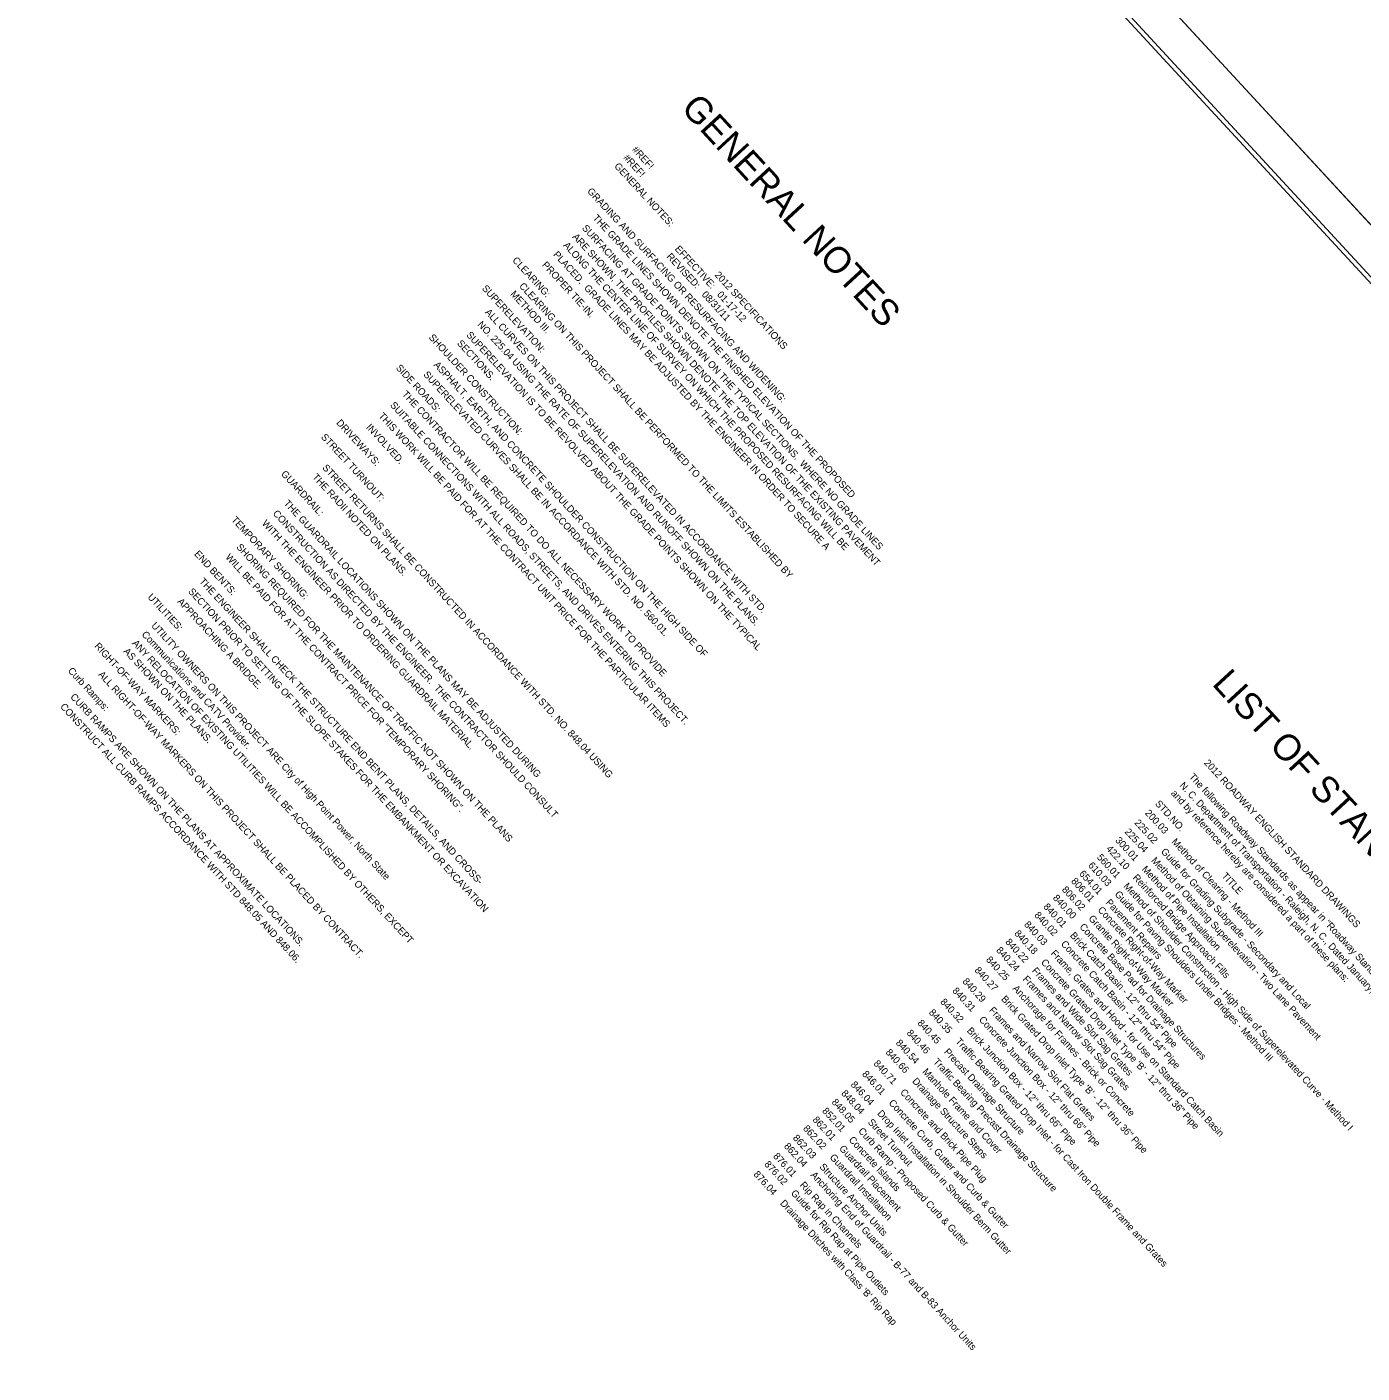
# Model space of a CAD drawing. Extents: x 1695041 to 1706254, y 786537 to 798223.
# Drawn here: x 1696581 to 1698101, y 794948 to 796480 of the extents above; entities that cross this region are included whole.
import ezdxf

# ---------------------------------------------------------------- set-up
doc = ezdxf.new("R2010")
doc.units = 0
for name, color, linetype in [('Old_Level_16', 7, 'Continuous'), ('Old_Level_23', 7, 'Continuous'), ('Sheet Cutting Line CELL', 7, 'Continuous'), ('Sheet Plan CELL', 7, 'Continuous'), ('Sheet Plot Border Inside CELL', 7, 'Continuous'), ('Sheet Plot Border Outside CELL', 7, 'Continuous')]:
    doc.layers.add(name, color=color, linetype=linetype)

msp = doc.modelspace()

# ---------------------------------------------------------------- linework, layer by layer
at = {"layer": 'Sheet Cutting Line CELL'}
msp.add_line((1698934.2, 795362), (1696650.4, 797836.1), dxfattribs=at)
at = {"layer": 'Sheet Plan CELL'}
msp.add_lwpolyline([(1698878.1, 795356.5), (1696843.2, 797560.9), (1695300.2, 796136.5), (1697335, 793932.1)], close=True, dxfattribs=at)
at = {"layer": 'Sheet Plot Border Inside CELL'}
msp.add_lwpolyline([(1695088.2, 796358.7), (1697348.3, 793910.3), (1698898.7, 795341.5), (1696638.7, 797789.9)], close=True, dxfattribs=at)
at = {"layer": 'Sheet Plot Border Outside CELL'}
msp.add_lwpolyline([(1695041.2, 796350.7), (1697325, 793876.6), (1698934.2, 795362), (1696650.4, 797836.1)], close=True, dxfattribs=at)

# ---------------------------------------------------------------- texts
at = {"layer": 'Old_Level_16'}
for s, p in [('                        GENERAL NOTES ', (1697143.1, 796582.8)), ('                        LIST OF STANDARD DRAWINGS ', (1697747.4, 795928.1))]:
    msp.add_text(s, height=30, rotation=312.7091, dxfattribs=at).set_placement(p)
at = {"layer": 'Old_Level_23'}
for s, p in [('#REF!', (1697269.5, 796339.4)), ('GENERAL NOTES:                         2012 SPECIFICATIONS', (1697249.2, 796320.7)), ('#REF!', (1697259.5, 796330.2)), ('GRADING AND SURFACING OR RESURFACING AND WIDENING:  ', (1697218.4, 796292.2)), ('         THE GRADE LINES SHOWN DENOTE THE FINISHED ELEVATION OF THE PROPOSED ', (1697206.6, 796281.4)), ('         SURFACING AT GRADE POINTS SHOWN ON THE TYPICAL SECTIONS.  WHERE NO GRADE LINES ', (1697194.3, 796270)), ('         ALONG THE CENTER LINE OF SURVEY ON WHICH THE PROPOSED RESURFACING WILL BE ', (1697173, 796250.3)), ('         ARE SHOWN, THE PROFILES SHOWN DENOTE THE TOP ELEVATION OF THE EXISTING PAVEMENT ', (1697183.4, 796260)), ('CLEARING:  ', (1697133.2, 796213.6)), ('         PLACED.  GRADE LINES MAY BE ADJUSTED BY THE ENGINEER IN ORDER TO SECURE A ', (1697161.6, 796239.8)), ('                                       REVISED:   08/31/11', (1697230.1, 796303.1)), ('                                       EFFECTIVE:   01-17-12', (1697239.5, 796311.7)), ('         PROPER TIE-IN.  ', (1697148.8, 796228)), ('SUPERELEVATION:  ', (1697098.6, 796181.7)), ('         CLEARING ON THIS PROJECT SHALL BE PERFORMED TO THE LIMITS ESTABLISHED BY ', (1697122.8, 796204)), ('         METHOD III.', (1697112.8, 796194.8)), ('         ALL CURVES ON THIS PROJECT SHALL BE SUPERELEVATED IN ACCORDANCE WITH STD. ', (1697083.9, 796174.2)), ('         NO. 225.04 USING THE RATE OF SUPERELEVATION AND RUNOFF SHOWN ON THE PLANS.', (1697075.4, 796160.2)), ('SHOULDER CONSTRUCTION:  ', (1697038.1, 796125.8)), ('         SUPERELEVATION IS TO BE REVOLVED ABOUT THE GRADE POINTS SHOWN ON THE TYPICAL ', (1697062.6, 796148.4)), ('         SECTIONS.  ', (1697052.1, 796138.8)), ('SIDE ROADS:  ', (1697000.7, 796091.3)), ('         ASPHALT, EARTH, AND CONCRETE SHOULDER CONSTRUCTION ON THE HIGH SIDE OF', (1697025.6, 796114.3)), ('         SUPERELEVATED CURVES SHALL BE IN ACCORDANCE WITH STD. NO. 560.01.', (1697013.8, 796103.3)), ('         THE CONTRACTOR WILL BE REQUIRED TO DO ALL NECESSARY WORK TO PROVIDE ', (1696989.6, 796081)), ('         SUITABLE CONNECTIONS WITH ALL ROADS, STREETS, AND DRIVES ENTERING THIS PROJECT.  ', (1696976, 796068.5)), ('DRIVEWAYS:  ', (1696932.9, 796028.7)), ('         THIS WORK WILL BE PAID FOR AT THE CONTRACT UNIT PRICE FOR THE PARTICULAR ITEMS ', (1696962.8, 796056.3)), ('         INVOLVED.  ', (1696948.7, 796043.3)), ('STREET TURNOUT:  ', (1696915.5, 796012.6)), ('GUARDRAIL:  ', (1696870, 795970.6)), ('         THE RADII NOTED ON PLANS.  ', (1696887.4, 795986.7)), ('         STREET RETURNS SHALL BE CONSTRUCTED IN ACCORDANCE WITH STD. NO. 848.04 USING ', (1696898.9, 795997.3)), ('         THE GUARDRAIL LOCATIONS SHOWN ON THE PLANS MAY BE ADJUSTED DURING ', (1696855, 795956.8)), ('         CONSTRUCTION AS DIRECTED BY THE ENGINEER.  THE CONTRACTOR SHOULD CONSULT', (1696842.5, 795945.3)), ('TEMPORARY SHORING:  ', (1696813.5, 795918.5)), ('         WITH THE ENGINEER PRIOR TO ORDERING GUARDRAIL MATERIAL.', (1696830.1, 795933.9)), ('END BENTS:  ', (1696771.3, 795879.5)), ('         WILL BE PAID FOR AT THE CONTRACT PRICE FOR "TEMPORARY SHORING".', (1696788.6, 795895.5)), ('         SHORING REQUIRED FOR THE MAINTENANCE OF TRAFFIC NOT SHOWN ON THE PLANS ', (1696801, 795907)), ('         THE ENGINEER SHALL CHECK THE STRUCTURE END BENT PLANS, DETAILS, AND CROSS-', (1696758.8, 795868)), ('UTILITIES:  ', (1696718.2, 795830.5)), ('         SECTION PRIOR TO SETTING OF THE SLOPE STAKES FOR THE EMBANKMENT OR EXCAVATION ', (1696746.3, 795856.5)), ('         APPROACHING A BRIDGE.  ', (1696733.9, 795845)), ('         UTILITY OWNERS ON THIS PROJECT ARE City of High Point Power, North State', (1696704.2, 795817.6)), ('         Communications and CATV Provider.', (1696693.3, 795807.6)), ('RIGHT-OF-WAY MARKERS:  ', (1696657.7, 795774.7)), ('         ANY RELOCATION OF EXISTING UTILITIES WILL BE ACCOMPLISHED BY OTHERS, EXCEPT ', (1696682.5, 795797.6)), ('         AS SHOWN ON THE PLANS.  ', (1696672.6, 795788.4)), ('Curb Ramps:', (1696627.4, 795746.7)), ('         ALL RIGHT-OF-WAY MARKERS ON THIS PROJECT SHALL BE PLACED BY CONTRACT.  ', (1696643.9, 795762)), ('        CURB RAMPS ARE SHOWN ON THE PLANS AT APPROXIMATE LOCATIONS.', (1696614.1, 795734.4)), ('        CONSTRUCT ALL CURB RAMPS ACCORDANCE WITH STD 848.05 AND 848.06.', (1696602.6, 795723.3)), ('2012 ROADWAY ENGLISH STANDARD DRAWINGS', (1697920.2, 795641.9)), ('N. C. Department of Transportation - Raleigh, N. C., Dated January, 2012 are applicable to this project', (1697892.4, 795616.2)), ('The following Roadway Standards as appear in "Roadway Standard Drawings" Highway Design Branch -', (1697903.1, 795626.1)), ('and by reference hereby are considered a part of these plans:', (1697882.6, 795607.2)), ('200.03    Method of Clearing - Method III', (1697853, 795584.8)), ('STD.NO.                       TITLE', (1697864.5, 795595.4)), ('225.02    Guide for Grading Subgrade - Secondary and Local', (1697840.9, 795573.7)), ('300.01    Method of Pipe Installation ', (1697819.2, 795553.7)), ('225.04    Method of Obtaining Superelevation - Two Lane Pavement', (1697829.9, 795563.5)), ('422.10    Reinforced Bridge Approach Fills', (1697808.9, 795544.1)), ('610.03    Guide for Paving Shoulders Under Bridges - Method III', (1697788.3, 795525.2)), ('560.01    Method of Shoulder Construction - High Side of Superelevated Curve - Method I', (1697798.3, 795534.3)), ('654.01    Pavement Repairs', (1697778.1, 795515.7)), ('806.02    Granite Right-of-Way Marker', (1697758.5, 795497.6)), ('806.01    Concrete Right-of-Way Marker', (1697769, 795507.3)), ('840.01    Brick Catch Basin - 12" thru 54" Pipe', (1697737.4, 795478.2)), ('840.00    Concrete Base Pad for Drainage Structures', (1697748.2, 795488.1)), ('840.02    Concrete Catch Basin - 12" thru 54" Pipe', (1697727.1, 795468.6)), ('840.18    Concrete Grated Drop Inlet Type \'B\' - 12" thru 36" Pipe', (1697704.4, 795447.7)), ('840.03    Frame, Grates and Hood - for Use on Standard Catch Basin', (1697715.5, 795457.9)), ('840.22    Frames and Wide Slot Sag Grates', (1697694.1, 795438.1)), ('840.25    Anchorage for Frames - Brick or Concrete', (1697672.1, 795417.9)), ('840.24    Frames and Narrow Slot Sag Grates', (1697683.7, 795428.6)), ('840.27    Brick Grated Drop Inlet Type \'B\' - 12" thru 36" Pipe', (1697659.1, 795405.9)), ('840.29    Frames and Narrow Slot Flat Grates', (1697645.4, 795393.2)), ('840.32    Brick Junction Box - 12" thru 66" Pipe', (1697620.1, 795369.9)), ('840.31    Concrete Junction Box - 12" thru 66" Pipe', (1697633.8, 795382.5)), ('840.35    Traffic Bearing Grated Drop Inlet - for Cast Iron Double Frame and Grates', (1697607.1, 795357.8)), ('840.45    Precast Drainage Structure', (1697594.1, 795345.8)), ('840.46    Traffic Bearing Precast Drainage Structure', (1697581.8, 795334.5)), ('840.66    Drainage Structure Steps', (1697557.9, 795312.5)), ('840.54    Manhole Frame and Cover', (1697569.5, 795323.2)), ('840.71    Concrete and Brick Pipe Plug', (1697544.2, 795299.8)), ('846.01    Concrete Curb, Gutter and Curb & Gutter', (1697531.2, 795287.8)), ('848.04    Street Turnout', (1697507.4, 795265.8)), ('846.04    Drop Inlet Installation in Shoulder Berm Gutter', (1697518.2, 795275.8)), ('848.05    Curb Ramp - Proposed Curb & Gutter', (1697496.5, 795255.8)), ('862.01    Guardrail Placement', (1697474.8, 795235.8)), ('852.01    Concrete Islands', (1697485.7, 795245.8)), ('862.02    Guardrail Installation', (1697464, 795225.8)), ('862.04    Anchoring End of Guardrail - B-77 and B-83 Anchor Units', (1697442.3, 795205.7)), ('862.03    Structure Anchor Units', (1697452.4, 795215.1)), ('876.01    Rip Rap in Channels', (1697430, 795194.4)), ("876.04    Drainage Ditches with Class 'B' Rip Rap", (1697407.6, 795173.7)), ('876.02    Guide for Rip Rap at Pipe Outlets', (1697419.9, 795185.1))]:
    msp.add_text(s, height=8, rotation=312.7091, dxfattribs=at).set_placement(p)

doc.saveas('drawing.dxf')
